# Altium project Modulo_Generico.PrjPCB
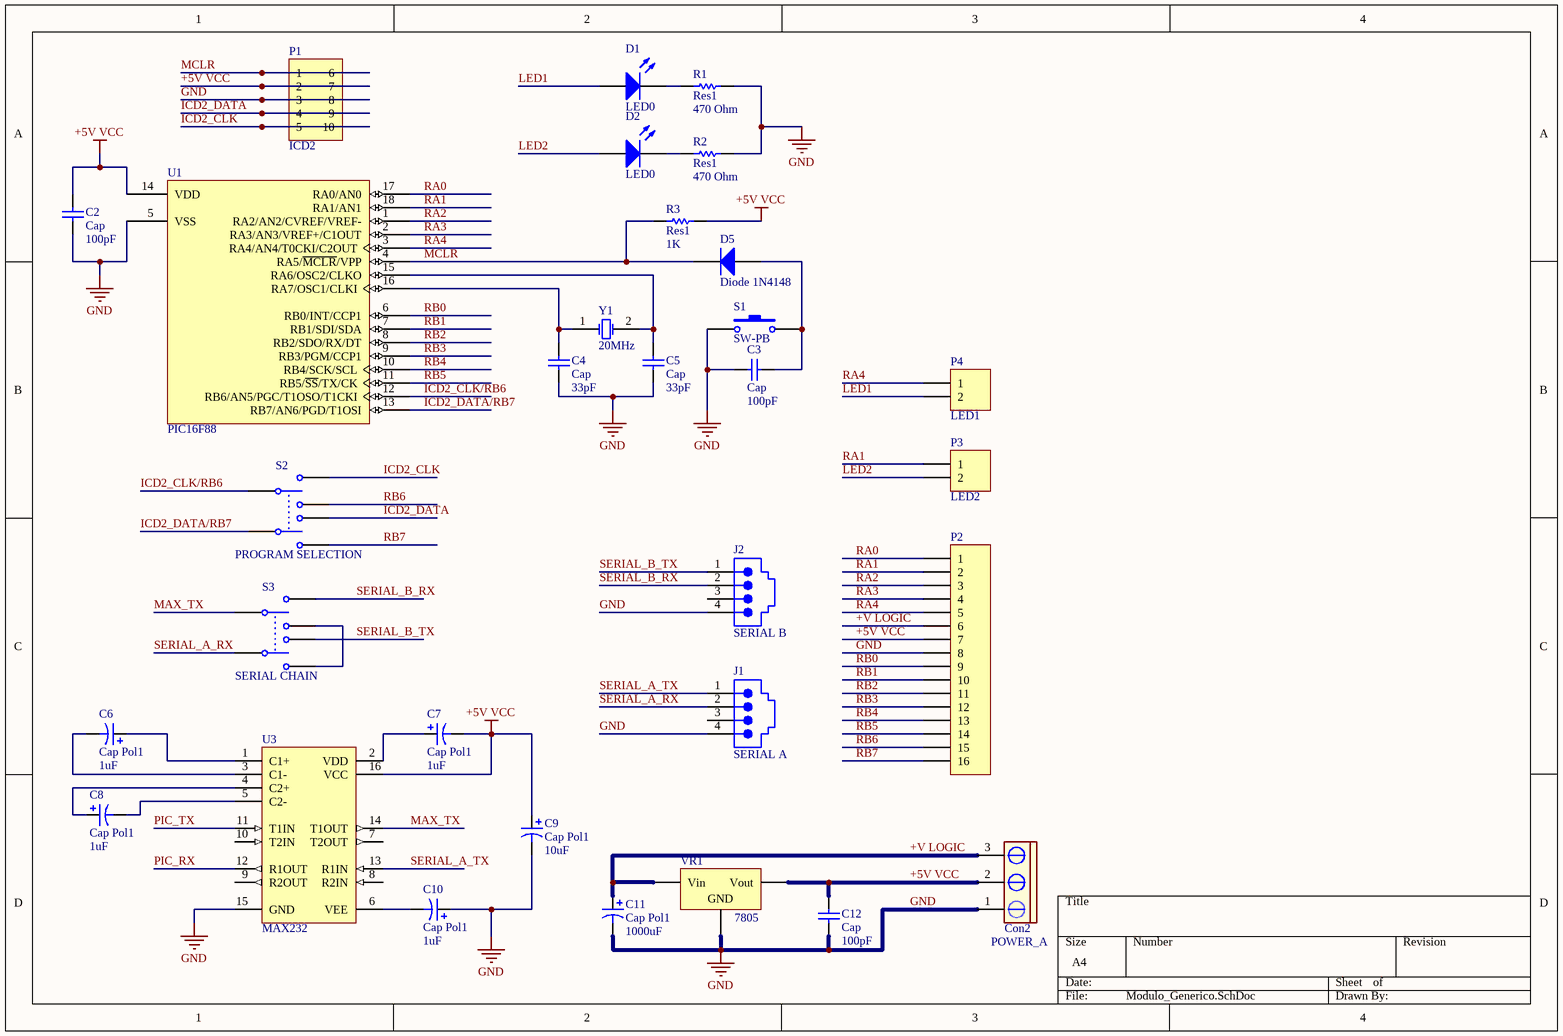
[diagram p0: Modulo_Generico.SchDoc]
1 sheet, 31 parts. Net scope: global (net labels, ports and power ports of the same name join across sheets).
Board file: Modulo_Generico.PcbDoc

## Sheet Modulo_Generico.SchDoc
size A4

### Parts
C2  Cap  value 100pF  [CAPR2.54-5.1x3.2]
C3  Cap  value 100pF  [CAPR2.54-5.1x3.2]
C4  Cap  value 33pF  [CAPR2.54-5.1x3.2]
C5  Cap  value 33pF  [CAPR2.54-5.1x3.2]
C6  Cap Pol1  value 1uF  [CAPPR2-5x6.8]
C7  Cap Pol1  value 1uF  [CAPPR2-5x6.8]
C8  Cap Pol1  value 1uF  [CAPPR2-5x6.8]
C9  Cap Pol1  value 10uF  [CAPPR2-5x6.8]
C10  Cap Pol1  value 1uF  [CAPPR2-5x6.8]
C11  Cap Pol1  value 1000uF  [RB5-10.5]
C12  Cap  value 100pF  [CAPR2.54-5.1x3.2]
Con2  POWER_A  [My_CN3]
D1  LED0  [LED-0]
D2  LED0  [LED-0]
D5  Diode 1N4148  [DIO7.1-3.9x1.9]
J1  SERIAL A  [15-43-6245]
J2  SERIAL B  [15-43-6245]
P1  ICD2  [HEADER10_5x2_B]
P2  Header 16  [My_1X16]  (value not drawn)
P3  LED2  [HDR1X2]
P4  LED1  [HDR1X2]
R1  Res1  value 470 Ohm  [AXIAL-0.3]
R2  Res1  value 470 Ohm  [AXIAL-0.3]
R3  Res1  value 1K  [AXIAL-0.3]
S1  SW-PB  [TS-063]
S2  PROGRAM SELECTION  [LD-202mini]
S3  SERIAL CHAIN  [LD-202mini]
U1  PIC16F88  [PDIP300-P18]
U3  MAX232  [PE16A]
VR1  7805  [My_TO-220]
Y1  20MHz  [My_Crystal]

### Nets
+5V VCC: C2.2 C7.2 C9.1 C12.2 Con2.2 P1.2 P1.7 P2.7 R3.2 U1.14(VDD) U3.16(VCC) VR1.3(Vout)
GND: C2.1 C3.1 C4.1 C5.1 C9.2 C10.1 C11.2 C12.1 Con2.1 J1.4 J2.4 P1.3 P1.8 P2.8 R1.2 R2.2 S1.1 U1.5(VSS) U3.15(GND) VR1.2(GND)
+V LOGIC: C11.1 Con2.3 P2.6 VR1.1(Vin)
ICD2_CLK: P1.5 P1.10 S2.2
ICD2_CLK/RB6: S2.1 U1.12(RB6/AN5/PGC/T1OSO/T1CKI)
ICD2_DATA: P1.4 P1.9 S2.5
ICD2_DATA/RB7: S2.4 U1.13(RB7/AN6/PGD/T1OSI)
LED1: D1.1(A) P4.2
LED2: D2.1(A) P3.2
MAX_TX: S3.1 U3.14(T1OUT)
MCLR: D5.2(K) P1.1 P1.6 R3.1 U1.4(RA5/~{MCLR}/VPP)
PIC_RX: U3.12(R1OUT)
PIC_TX: U3.11(T1IN)
RA0: P2.1 U1.17(RA0/AN0)
RA1: P2.2 P3.1 U1.18(RA1/AN1)
RA2: P2.3 U1.1(RA2/AN2/CVREF/VREF-)
RA3: P2.4 U1.2(RA3/AN3/VREF+/C1OUT)
RA4: P2.5 P4.1 U1.3(RA4/AN4/T0CKI/C2OUT)
RB0: P2.9 U1.6(RB0/INT/CCP1)
RB1: P2.10 U1.7(RB1/SDI/SDA)
RB2: P2.11 U1.8(RB2/SDO/RX/DT)
RB3: P2.12 U1.9(RB3/PGM/CCP1)
RB4: P2.13 U1.10(RB4/SCK/SCL)
RB5: P2.14 U1.11(RB5/~{SS}/TX/CK)
RB6: P2.15 S2.3
RB7: P2.16 S2.6
SERIAL_A_RX: J1.2 S3.4
SERIAL_A_TX: J1.1 U3.13(R1IN)
SERIAL_B_RX: J2.2 S3.2
SERIAL_B_TX: J2.1 S3.5
NetC3_2: C3.2 D5.1(A) S1.2
NetC4_2: C4.2 U1.16(RA7/OSC1/CLKI) Y1.1(OSC1)
NetC5_2: C5.2 U1.15(RA6/OSC2/CLKO) Y1.2(OSC2)
NetC6_1: C6.1 U3.1(C1+)
NetC6_2: C6.2 U3.3(C1-)
NetC7_1: C7.1 U3.2(VDD)
NetC8_1: C8.1 U3.4(C2+)
NetC8_2: C8.2 U3.5(C2-)
NetC10_2: C10.2 U3.6(VEE)
NetD1_2: D1.2(K) R1.1
NetD2_2: D2.2(K) R2.1
NetS3_3: S3.3 S3.6

Not connected (* = marked no-connect by the designer): J1 3; J2 3; U3 7(T2OUT) 8(R2IN) 9(R2OUT) 10(T2IN)

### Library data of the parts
C2-C5 C12 = Cap: Capacitor
C6-C11 = Cap Pol1: Polarized Capacitor (Radial)
Con2 = CON3 pin Green: Connector green screw
D1 D2 = LED0: Typical INFRARED GaAs LED
D5 = Diode 1N4148: High Conductance Fast Diode
J1 J2 = 15-43-6245: Right Angle, Standard Profile, RJ45-Keyed, Flange Mount PCB Jack; Ports: 1; Positions/Loaded: Port1 - 8 Keyed/4; PerformanceCategory: 3; PCB_Mounting: Thru-Hole; ComponentAvailability: Obsolete; DrillSize: Nominal, Rounded to nearest 0.05mm; PCB_Layout: Complies with Manufacturer's Recommendation.
P1 = Header 5X2A: Header, 5-Pin, Dual row
P2 = Header 16: Header, 16-Pin
P3 P4 = Header 2: Header, 2-Pin
R1-R3 = Res1: Resistor
S1 = SW-PB: Switch
S2 S3 = SW-DPDT: Double-Pole, Double-Throw Switch
U1 = PIC16F88-E/P: Enhanced FLASH Microcontroller with nanoWatt Technology, 10-Bit A/D, 4K (x14-Bit words) FLASH, 368 Bytes RAM, 18-Pin PDIP, Standard VDD Range, Extended Temperature; Note: The CCP1 pin is determined by CCPMX in Configuration Word 1 register.
U3 = MAX232ACPE: +5V Powered, Multi-Channel RS-232 Driver/Receiver
VR1 = Volt Reg: Voltage Regulator
Y1 = XTAL: Crystal Oscillator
